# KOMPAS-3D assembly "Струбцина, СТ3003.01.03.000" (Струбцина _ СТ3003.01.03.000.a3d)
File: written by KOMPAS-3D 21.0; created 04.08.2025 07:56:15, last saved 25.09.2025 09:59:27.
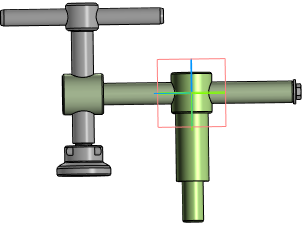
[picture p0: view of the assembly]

Document properties: Полное имя файла: C:\Users\1\Yandex.Disk\Документы\Новая папка\Стапель №2\Стапель _ СТ3003.00.00.000\Опора _ СТ3003.01.00.000\3D\Струбцина _ СТ3003.01.03.000\Струбцина _ СТ3003.01.03.000.a3d; Автор: 1

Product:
- Part/product: Струбцина  | designation СТ3003.01.03.000
    Масса: 1.103282
    Форматы листов документа: A3
  - Component [standard]: Винт с шестигранной головкой ГОСТ Р ИСО 4017-М6 x 25-5.8-A2P  | pos. 8  | Материал: Сталь (density 1000 kg/m3); Масса: 0.001042; Раздел спецификации: Стандартные изделия; Рассекать на разрезах: no; additional columns: ГОСТ Р ИСО 4017-2013; М6 x 25 - 5.8 - A2P
  - Component [standard]: Шайба A 6.01.10.019 ГОСТ 6958-78  | pos. 6  | Масса: 0.002792; Раздел спецификации: Стандартные изделия; Рассекать на разрезах: no
  - Component [detail]: Опора  | designation СТ3003.01.03.001  | pos. 1  | Материал: Круг$d30 ГОСТ 2590-2006;40Х ГОСТ 4543-2016$ (density 7850 kg/m3); Масса: 0.339602; Форматы листов документа: A4; source file: ..\..\2D\Струбцина _ СТ3003.01.03.000\Опора _ СТ3003.01.03.001.cdw, Опора _ СТ3003.01.03.001.m3d
  - Component [detail]: Ось  | designation СТ3003.01.03.002  | pos. 2  | Материал: Круг$d30 ГОСТ 2590-2006;40Х ГОСТ 4543-2016$ (density 7850 kg/m3); Масса: 0.346686; Форматы листов документа: A4; source file: ..\..\2D\Струбцина _ СТ3003.01.03.000\Ось _ СТ3003.01.03.002.cdw, Ось _ СТ3003.01.03.002.m3d
  - Component [standard]: Винт 7006-0537 ГОСТ 13431-68  | pos. 4  | Материал: Сталь 40Х ГОСТ 4543-2016 (density 1000 kg/m3); Масса: 0.294; Раздел спецификации: Стандартные изделия; Рассекать на разрезах: no; additional columns: 7006-0537
  - Component [standard]: Пята 7007-0035 ГОСТ 13437-68  | pos. 5  | Материал: Сталь 40Х ГОСТ 4543-2016 (density 1000 kg/m3); Масса: 0.116; Раздел спецификации: Стандартные изделия; Рассекать на разрезах: no; additional columns: 7007-0035
  - Component [standard]: Штифт 4x16 ГОСТ 3128-70  | qty 2  | pos. 7  | Материал: Сталь 45 ГОСТ 1050-88 (density 1000 kg/m3); Масса: 0.00158; Раздел спецификации: Стандартные изделия; Рассекать на разрезах: no
- Part/product: Струбцина  | designation СТ3003.01.03.000-01
    Масса: 1.075052
  - Component [standard]: Болт М6-6gx25.58.019 ГОСТ 7798-70  | pos. 5  | Масса: 0.007871; Раздел спецификации: Стандартные изделия; Рассекать на разрезах: no
  - Component [standard]: Шайба A 6.01.10.019 ГОСТ 6958-78  | pos. 6  | Масса: 0.002792; Раздел спецификации: Стандартные изделия; Рассекать на разрезах: no
  - Component [standard]: Штифт 4x16 ГОСТ 3128-70  | qty 2  | pos. 7  | Материал: Сталь 45 ГОСТ 1050-88 (density 1000 kg/m3); Масса: 0.00158; Раздел спецификации: Стандартные изделия; Рассекать на разрезах: no
  - Component [standard]: Пята 7007-0035 ГОСТ 13437-68  | pos. 5  | Материал: Сталь 40Х ГОСТ 4543-2016 (density 1000 kg/m3); Масса: 0.116; Раздел спецификации: Стандартные изделия; Рассекать на разрезах: no; additional columns: 7007-0035
  - Component [standard]: Винт 7006-0537 ГОСТ 13431-68  | pos. 4  | Материал: Сталь 40Х ГОСТ 4543-2016 (density 1000 kg/m3); Масса: 0.294; Раздел спецификации: Стандартные изделия; Рассекать на разрезах: no; additional columns: 7006-0537
  - Component [detail]: Ось  | designation СТ3003.01.03.002  | pos. 2  | Материал: Круг$d30 ГОСТ 2590-2006;40Х ГОСТ 4543-2016$ (density 7850 kg/m3); Масса: 0.346686; Форматы листов документа: A4; source file: ..\..\2D\Струбцина _ СТ3003.01.03.000\Ось _ СТ3003.01.03.002.cdw, Ось _ СТ3003.01.03.002.m3d
  - Component [detail]: Опора  | designation СТ3003.01.03.001  | pos. 1  | Материал: Круг$d30 ГОСТ 2590-2006;40Х ГОСТ 4543-2016$ (density 7850 kg/m3); Масса: 0.339602; Форматы листов документа: A4; source file: ..\..\2D\Струбцина _ СТ3003.01.03.000\Опора _ СТ3003.01.03.001.cdw, Опора _ СТ3003.01.03.001.m3d
- Part/product: Струбцина  | designation СТ3003.01.03.000-02
    Масса: 1.075052
  - Component [detail]: Опора  | designation СТ3003.01.03.001  | pos. 1  | Материал: Круг$d30 ГОСТ 2590-2006;40Х ГОСТ 4543-2016$ (density 7850 kg/m3); Масса: 0.339602; Форматы листов документа: A4; source file: ..\..\2D\Струбцина _ СТ3003.01.03.000\Опора _ СТ3003.01.03.001.cdw, Опора _ СТ3003.01.03.001.m3d
  - Component [detail]: Ось  | designation СТ3003.01.03.002  | pos. 2  | Материал: Круг$d30 ГОСТ 2590-2006;40Х ГОСТ 4543-2016$ (density 7850 kg/m3); Масса: 0.346686; Форматы листов документа: A4; source file: ..\..\2D\Струбцина _ СТ3003.01.03.000\Ось _ СТ3003.01.03.002.cdw, Ось _ СТ3003.01.03.002.m3d
  - Component [standard]: Винт 7006-0537 ГОСТ 13431-68  | pos. 4  | Материал: Сталь 40Х ГОСТ 4543-2016 (density 1000 kg/m3); Масса: 0.294; Раздел спецификации: Стандартные изделия; Рассекать на разрезах: no; additional columns: 7006-0537
  - Component [standard]: Пята 7007-0035 ГОСТ 13437-68  | pos. 5  | Материал: Сталь 40Х ГОСТ 4543-2016 (density 1000 kg/m3); Масса: 0.116; Раздел спецификации: Стандартные изделия; Рассекать на разрезах: no; additional columns: 7007-0035
  - Component [standard]: Штифт 4x16 ГОСТ 3128-70  | qty 2  | pos. 7  | Материал: Сталь 45 ГОСТ 1050-88 (density 1000 kg/m3); Масса: 0.00158; Раздел спецификации: Стандартные изделия; Рассекать на разрезах: no
  - Component [standard]: Шайба A 6.01.10.019 ГОСТ 6958-78  | pos. 6  | Масса: 0.002792; Раздел спецификации: Стандартные изделия; Рассекать на разрезах: no
  - Component [standard]: Болт М6-6gx25.58.019 ГОСТ 7798-70  | pos. 5  | Масса: 0.007871; Раздел спецификации: Стандартные изделия; Рассекать на разрезах: no

Referenced files in C:\Users\1\Yandex.Disk\Документы\Новая папка\Стапель №2\Стапель _ СТ3003.00.00.000\Опора _ СТ3003.01.00.000\3D\Струбцина _ СТ3003.01.03.000\: Ось _ СТ3003.01.03.002.m3d, Опора _ СТ3003.01.03.001.m3d
Referenced files in C:\Users\1\Yandex.Disk\Документы\Новая папка\Стапель №2\Стапель _ СТ3003.00.00.000\Опора _ СТ3003.01.00.000\2D\Струбцина _ СТ3003.01.03.000\: Ось _ СТ3003.01.03.002.cdw, Опора _ СТ3003.01.03.001.cdw
Referenced files in C:\Program Files\ASCON\KOMPAS-3D v21\Libs\PartLib\DATA\VAULT\Methods\Kompas\3D\: PLib_Piata_GOST_13437-68_813.m3d, PLib_Pin_3128_712.m3d, PLib_Bolt_1_900.m3d
Referenced files in C:\Program Files\ASCON\KOMPAS-3D v21\Libs\PARTLib\DATA\vault\Methods\Kompas\3D\: PLib_Washer_1_712.m3d, PLib_Bolt_1_ISO_1100.m3d, PLib_Pin_3128_712.m3d
Referenced files in C:\Program Files\ASCON\KOMPAS-3D v21\Libs\PARTLib\DATA\vault\Methods\Kompas\3D\Holding_devices\13447_13430_13431_13426_8921\: Plib_Screw_GOST_13431-68_813.a3d
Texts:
  СТ3003.01.03.002
  СТ3003.01.03.001
  Элемент станочного приспособления
  Крепежное изделие ГОСТ
  Круг$d30 ГОСТ 2590-2006;Ст3сп ГОСТ 535-2005$
  Винт с шестигранной головкой
  ГОСТ Р ИСО
  СТ3003.01.03.000
  СТ3003.01.03.001 Опора
  СТ3003.01.03.002 Ось
  Isp1
  Isp2
  Isp3
  Штифт 4x16 ГОСТ 3128-70 (1)
  Штифт 4x16 ГОСТ 3128-70 (2)
  hole1
  hole2
  Канавка на торце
